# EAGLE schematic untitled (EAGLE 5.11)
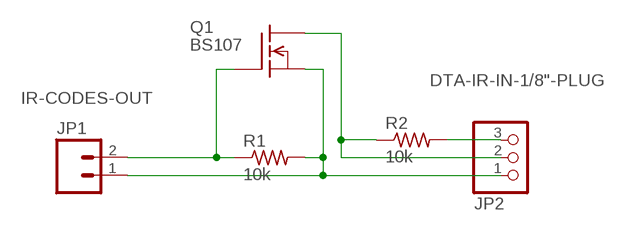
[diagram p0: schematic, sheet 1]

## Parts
JP1  M02POLAR  [MOLEX-1X2]
JP2  PINHD-1X3  [1X03]
Q1  BS107  TN0604N3  [TO-92]
R1  10k  R-US_R0805  [R0805]
R2  10k  R-US_R0805  [R0805]

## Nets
N$1: JP1.1 JP2.1 Q1.1(S) R1.2
N$2: JP1.2 Q1.2(G) R1.1
N$3: JP2.2 Q1.3(D) R2.1
N$4: JP2.3 R2.2

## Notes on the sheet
- DTA-IR-IN-1/8"-PLUG
- IR-CODES-OUT

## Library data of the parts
JP1 = SparkFun:M02: Header 2
JP2 = pinhead:PINHD-1X3: PIN HEADER
Q1 = transistor-fet:TN0604N3: N-Channel Enhancement MOSFET 40V; 4A; 0,75Ohm
R1 R2 = resistor:R-US_: RESISTOR, American symbol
